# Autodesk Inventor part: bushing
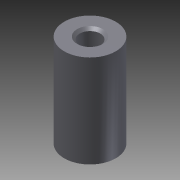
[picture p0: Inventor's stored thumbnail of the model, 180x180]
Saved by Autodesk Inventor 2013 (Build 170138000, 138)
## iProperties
Shininess: 64.0
Length Units: 11269
Angle Units: 11279
Time Units: 11290
Mass Units: 11283
Length Display Precision: 3
Angle Display Precision: 2
Compacted: True
Part Number: bushing
Document SubType Name: Modeling
Created: 2004-03
Material: Steel, Mild
Designer: =<Author>
Manufacturer: Standard
Standards Organization: Custom
Description: =<Part Number>
Density: 7.86 g/cm^3
Mass: 74.4574 g
Surface Area: 36.6767 cm^2
Volume: 9.47295 cm^3
Density: 0.0
Volumn: 0.0
Area: 0.0
PropertySet Name: Model Information
Control State: 0
Master: False
Checked Out: False
Checked Out Date: 2008-10-15
Last Check In Date: 2008-10-15
d0: 8.000 mm
d1: 20.000 mm
d2: 36.000 mm
d3: 0.00 deg
d4: 1.000 mm
Author: PVitaliy
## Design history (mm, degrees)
sketch "Эскиз1"
  geometry: C1 r 10 at (0, 0); C2 r 4 at (0, 0)
  constraints: 2 centre point, 1 coincident, 1 other
  dimensions: "d0" = 8 diameter of C2; "d1" = 20 diameter of C1
extrude "Выдавливание1" new body sketch "Эскиз1" distance "d2" = 36; taper "d3" = 0 deg
chamfer "Фаска1" distance "d4" = 1; stored, may be unused: second distance "d5" = 2, angle "d6" = 45 deg
body "Solid1"
